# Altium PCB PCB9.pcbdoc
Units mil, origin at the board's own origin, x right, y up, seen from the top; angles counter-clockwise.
Board outline 4294.33 x 816.76 mil, 2 copper layers (Top Layer, Bottom Layer); 2 components, 2 nets, 10 pads, 0 vias.
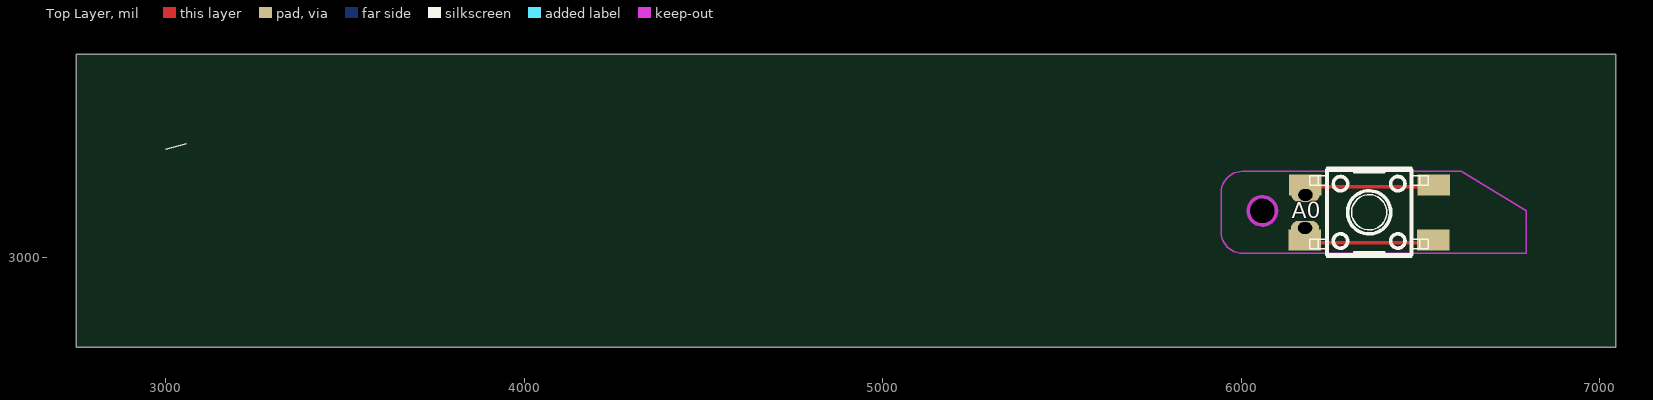
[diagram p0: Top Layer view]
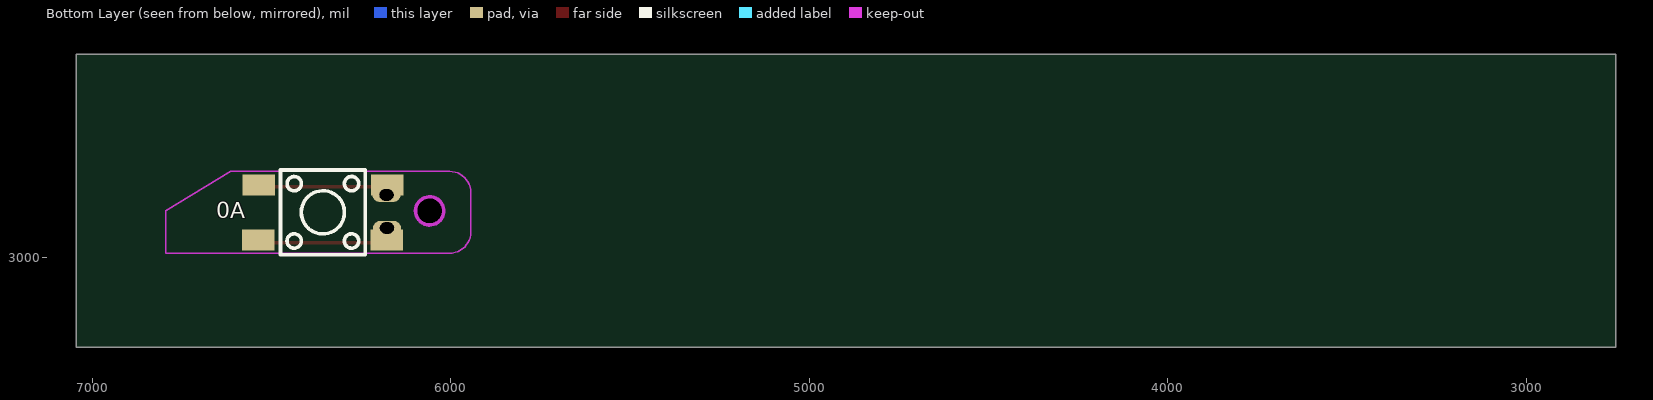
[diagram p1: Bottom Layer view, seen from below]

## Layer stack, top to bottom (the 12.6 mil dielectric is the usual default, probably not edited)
Top Layer: signal copper (thickness not stored)
Dielectric: dielectric 12.6, FR-4, Dk 4.8
Bottom Layer: signal copper (thickness not stored)

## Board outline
7044.33,2750 2750,2750 2750,3566.76 7044.33,3566.76
cut-out: 6097.98,3129.88 ccw(c6058.61,3129.88) 6019.24,3129.88 ccw(c6058.61,3129.88)

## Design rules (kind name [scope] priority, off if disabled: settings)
BoardOutlineClearance copperThickness1oz [All] p0: genericclearance=10 ignorepadtopadclearanceinfootprint=FALSE except(0: Arc-SplitContinuation Track-SplitContinuation SMDPad-SplitContinuation THPad-SplitContinuation Via-SplitContinuation Fill-SplitContinuation Poly-SplitContinuation Region-SplitContinuation Text-SplitContinuation; 6: SMDPad-CutoutEdge THPad-CutoutEdge Via-CutoutEdge Fill-CutoutEdge Region-CutoutEdge; 11.8: Track-OutlineEdge SMDPad-OutlineEdge THPad-OutlineEdge Via-OutlineEdge Fill-OutlineEdge Region-OutlineEdge Poly-OutlineEdge Text-OutlineEdge Track-CutoutEdge)
BoardOutlineClearance copperThickness2oz [All] p0: genericclearance=10 ignorepadtopadclearanceinfootprint=FALSE except(0: Arc-SplitContinuation Track-SplitContinuation SMDPad-SplitContinuation THPad-SplitContinuation Via-SplitContinuation Fill-SplitContinuation Poly-SplitContinuation Region-SplitContinuation Text-SplitContinuation; 6: SMDPad-CutoutEdge THPad-CutoutEdge Via-CutoutEdge Fill-CutoutEdge Region-CutoutEdge; 11.8: Track-OutlineEdge SMDPad-OutlineEdge THPad-OutlineEdge Via-OutlineEdge Fill-OutlineEdge Region-OutlineEdge Poly-OutlineEdge Text-OutlineEdge Track-CutoutEdge)
Clearance copperThickness1oz [(InNet('GND') OR InNet('A0'))] p1: gap=7 ignorepadtopadclearanceinfootprint=FALSE except(4: Track-Track; 6: Track-SMDPad SMDPad-SMDPad Track-THPad SMDPad-THPad THPad-THPad Track-Via SMDPad-Via THPad-Via Via-Via Track-Fill SMDPad-Fill THPad-Fill Via-Fill Fill-Fill SMDPad-Region THPad-Region Via-Region Fill-Region Region-Region Track-Poly SMDPad-Poly THPad-Poly Via-Poly Fill-Poly Poly-Poly Track-Text SMDPad-Text THPad-Text Via-Text Fill-Text Region-Text Poly-Text Text-Text Track-Hole SMDPad-Hole THPad-Hole Via-Hole Fill-Hole Region-Hole Poly-Hole Text-Hole; 11.8: Track-Region Region-Poly Track-Sheet SMDPad-Sheet THPad-Sheet Via-Sheet Fill-Sheet Region-Sheet Poly-Sheet Text-Sheet Sheet-Hole)
Clearance copperThickness2oz [All] p1: gap=7 ignorepadtopadclearanceinfootprint=FALSE except(6: Track-SMDPad SMDPad-SMDPad Track-THPad SMDPad-THPad THPad-THPad Track-Via SMDPad-Via THPad-Via Via-Via Track-Fill SMDPad-Fill THPad-Fill Via-Fill Fill-Fill SMDPad-Region THPad-Region Via-Region Fill-Region Region-Region Track-Poly SMDPad-Poly THPad-Poly Via-Poly Fill-Poly Poly-Poly Track-Text SMDPad-Text THPad-Text Via-Text Fill-Text Region-Text Poly-Text Text-Text Track-Hole SMDPad-Hole THPad-Hole Via-Hole Fill-Hole Region-Hole Poly-Hole Text-Hole; 8: Track-Track; 11.8: Track-Region Region-Poly Track-Sheet SMDPad-Sheet THPad-Sheet Via-Sheet Fill-Sheet Region-Sheet Poly-Sheet Text-Sheet Sheet-Hole)
DiffPairsRouting differentialPair [All] p1: maxuncoupledlength=10 minlimit=5.9843 maxlimit=5.9843 mostfreqgap=5.9843 toplayer_minwidth=5 toplayer_prefwidth=10 toplayer_maxwidth=100 bottomlayer_minwidth=5 bottomlayer_prefwidth=10 bottomlayer_maxwidth=100
PasteMaskExpansion pasteMaskExpansion [All] p1: expansion=0
PlaneConnect innerPlane [All] p1: planeconnectstyle=Relief reliefexpansion=20 reliefentries=4 reliefconductorwidth=10 reliefairgap=10
PolygonConnect copperRegion [All] p1: connectstyle=Direct reliefentries=4 reliefconductorwidth=10 polygonreliefangle="90 Angle" airgapwidth=10
RoutingVias viaSize [All] p1: viastyle="Through Hole" holewidth=12.0078 minholewidth=11.811 maxholewidth=248.0314 width=24.0158 minwidth=19.685 maxwidth=393.7008
SolderMaskExpansion solderMaskExpansion [All] p1: useseparateexpansions=TRUE expansion=2.0079 expansionbottom=2.0079
Width copperThickness1oz [All] p1: maxlimit=100 minlimit=5 preferedwidth=10
Width copperThickness2oz [All] p1: maxlimit=100 minlimit=8 preferedwidth=10

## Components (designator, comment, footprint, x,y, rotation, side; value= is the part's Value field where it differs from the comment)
A0 "按键" sw-smd_4p-l6.0-w6.0-p4.50-ls9.0-2 6356.42,3125.86 r180 bottom
A0 "按键" sw-smd_4p-l6.0-w6.0-p4.50-ls9.0-2 6356.42,3125.86 r0 top

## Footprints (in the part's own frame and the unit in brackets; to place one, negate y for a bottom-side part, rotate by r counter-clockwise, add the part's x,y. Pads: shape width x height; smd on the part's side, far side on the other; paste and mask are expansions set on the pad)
sw-smd_4p-l6.0-w6.0-p4.50-ls9.0-2 [mm]
  rect 2.3x1.5 smd: 1(-4.533,1.94) 2(4.567,1.94) 3(-4.567,-1.973) 4(4.533,-1.973)
  silkscreen extent -3,-3 3,3

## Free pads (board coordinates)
  oval 78.74x39.37 hole 31.5 slot 39.37 at 0 deg: 9(6177.58,3082.21) 9(6178.9,3174.39)

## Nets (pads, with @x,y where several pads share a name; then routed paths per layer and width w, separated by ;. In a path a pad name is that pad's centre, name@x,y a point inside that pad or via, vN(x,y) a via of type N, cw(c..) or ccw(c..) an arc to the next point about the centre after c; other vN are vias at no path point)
A0: A0.1 A0.2 pad.9@6178.9,3174.39 | length 387.6
  Top Layer w10: pad.9@6174.18,3181.94 6189.98,3197.74 A0.2@6555.19,3197.74
GND: A0.3 A0.4 pad.9@6177.58,3082.21 | length 361.8
  Top Layer w10: pad.9@6168.03,3071.32 6197.88,3041.47 A0.4@6517.44,3041.47

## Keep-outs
Board Outline Layer:
  circle w1: c6058.61,3129.88 r39.37
  circle w10: c6058.61,3129.88 r39.37
  lines w3.94: 6237.19,3011.81 6794.33,3011.81 6794.33,3129.9 6613.73,3240.12 6237.87,3240.12 ; 6238.42,3011.81 6002.99,3011.81 cw(c6002.99,3070.87) 5943.93,3070.87 5943.93,3181.11 cw(c6002.99,3181.11) 6002.99,3240.16 6238.42,3240.15

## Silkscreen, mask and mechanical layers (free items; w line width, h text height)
Top Silkscreen Layer:
  circle w3.94: c6356.53,3125.98 r59.05
  circle w3.94: c6356.53,3125.98 r49.21
  lines w3.94: 3000,3301.47 3057.04,3316.76 ; 6214.8,3023.62 6214.8,3051.18 ; 6214.8,3200.79 6214.8,3228.35 ; 6475.04,3023.62 6521.89,3023.62 6521.89,3051.18 6475.04,3051.18 ; 6475.04,3200.79 6521.89,3200.79 6521.89,3228.35 6475.04,3228.35 ; 6498.26,3023.62 6498.26,3051.18 ; 6498.26,3200.79 6498.26,3228.35 ; 6238.42,3000 6238.42,3051.18 6191.18,3051.18 6191.18,3023.62 6238.42,3023.62 6238.42,3228.35 6191.18,3228.35 6191.18,3200.79 6238.42,3200.79 6238.42,3251.97 ; 6238.42,3000 6242.36,3003.94 ; 6238.42,3000 6395.9,3000 ; 6238.42,3251.97 6474.64,3251.97 ; 6238.42,3251.97 6242.36,3248.03 ; 6242.36,3003.94 6313.23,3003.94 ; 6242.36,3003.94 6242.36,3248.03 ; 6242.36,3248.03 6313.23,3248.03 ; 6313.23,3003.94 6317.16,3000 ; 6313.23,3003.94 6313.23,3015.75 ; 6313.23,3015.75 6399.84,3015.75 ; 6313.23,3015.75 6317.16,3011.81 ; 6313.23,3236.22 6399.84,3236.22 ; 6313.23,3236.22 6317.16,3240.16 ; 6313.23,3236.22 6313.23,3248.03 ; 6313.23,3248.03 6317.16,3251.97 6317.16,3240.16 ; 6317.16,3000 6317.16,3011.81 ; 6317.16,3000 6474.64,3000 ; 6317.16,3011.81 6395.9,3011.81 ; 6317.16,3240.16 6395.9,3240.16 ; 6395.9,3000 6399.84,3003.94 ; 6395.9,3000 6395.9,3011.81 ; 6395.9,3011.81 6399.84,3015.75 ; 6395.9,3240.16 6399.84,3236.22 ; 6395.9,3240.16 6395.9,3251.97 6399.84,3248.03 ; 6399.84,3003.94 6470.71,3003.94 ; 6399.84,3003.94 6399.84,3015.75 ; 6399.84,3236.22 6399.84,3248.03 ; 6399.84,3248.03 6470.71,3248.03 ; 6470.71,3003.94 6474.64,3000 ; 6470.71,3003.94 6470.71,3248.03 ; 6470.71,3248.03 6474.64,3251.97 ; 6474.64,3000 6474.64,3251.97
Mechanical Layer:
  circle w1: c6058.61,3129.88 r39.37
